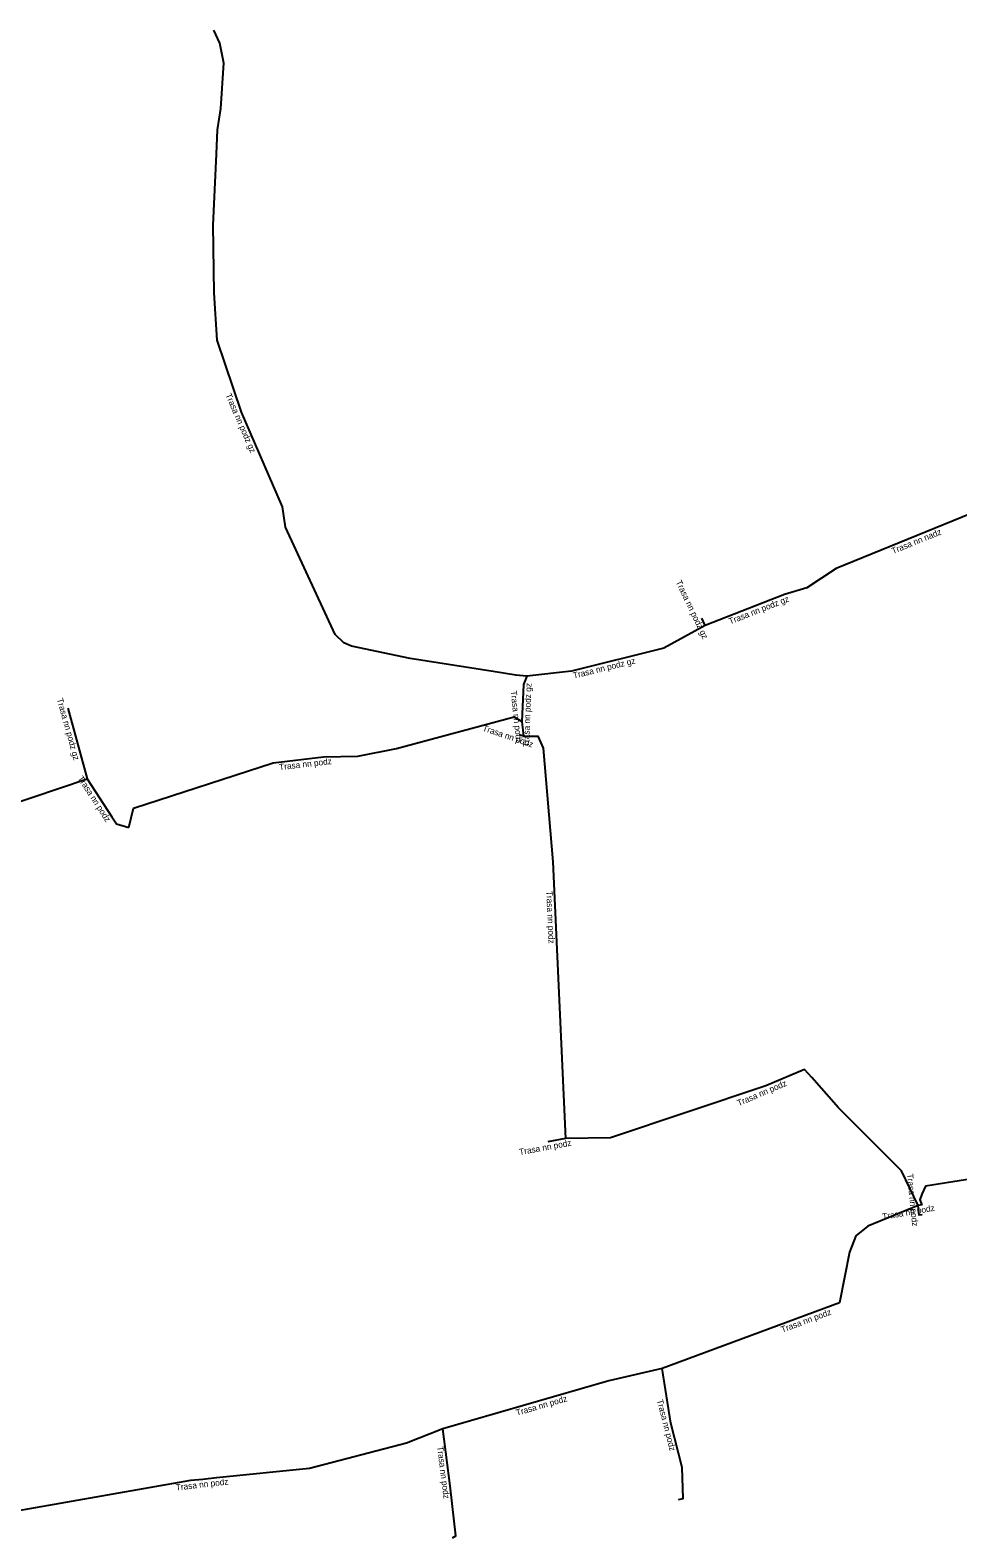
# Model space of a CAD drawing. Extents: x -682605 to -681948, y -1059884 to -1059661.
# Drawn here: x -682078.5 to -682003.5, y -1059783.1 to -1059661.3 of the extents above; entities that cross this region are included whole.
import ezdxf

# ---------------------------------------------------------------- set-up
doc = ezdxf.new("R2010")
doc.units = 0
doc.layers.add('Popiskový text - Ostatní atributy Trasy', color=7, linetype='Continuous')
doc.layers.add('Spojnice NN', color=7, linetype='Continuous')

msp = doc.modelspace()

# ---------------------------------------------------------------- linework, layer by layer
at = {"layer": 'Spojnice NN'}
for points in [[(-682038.37, -1059713.5), (-682039.26, -1059713.42), (-682041.09, -1059713.12), (-682047.78, -1059712.07), (-682052.52, -1059711.08), (-682053.14, -1059710.79), (-682053.84, -1059710.14), (-682057.85, -1059701.45), (-682058.11, -1059699.81), (-682061.41, -1059692.17), (-682063.38, -1059686.35), (-682063.62, -1059682.53), (-682063.69, -1059677.06), (-682063.44, -1059671.32), (-682063.35, -1059669.36), (-682063.08, -1059667.63), (-682062.85, -1059663.98), (-682063.16, -1059662.34), (-682063.64, -1059661.3)], [(-681998.83, -1059698.88), (-682013.37, -1059704.8)], [(-682013.37, -1059704.8), (-682015.73, -1059706.36), (-682017.53, -1059706.9), (-682023.94, -1059709.41)], [(-682023.94, -1059709.41), (-682024.22, -1059708.82)], [(-682023.94, -1059709.41), (-682027.3, -1059711.23), (-682034.75, -1059713.08), (-682038.37, -1059713.5)], [(-682038.37, -1059713.5), (-682038.63, -1059714.17), (-682038.75, -1059717.15)], [(-682075.45, -1059716.08), (-682073.88, -1059721.78)], [(-682070.52, -1059725.73), (-682070.13, -1059724.17), (-682058.84, -1059720.49), (-682054.79, -1059720.02), (-682052, -1059719.96), (-682048.89, -1059719.33), (-682039.37, -1059716.77), (-682038.75, -1059717.15)], [(-682038.75, -1059717.15), (-682038.62, -1059718.35)], [(-682038.62, -1059718.35), (-682038.97, -1059718.23)], [(-682038.62, -1059718.35), (-682037.46, -1059718.35), (-682037.04, -1059719.3), (-682036.25, -1059728.49), (-682035.24, -1059750.85)], [(-682090.02, -1059727.12), (-682082.85, -1059724.8), (-682073.88, -1059721.78)], [(-682073.88, -1059721.78), (-682071.89, -1059724.86), (-682071.52, -1059725.41), (-682070.52, -1059725.73)], [(-682006.74, -1059756.26), (-682008.1, -1059753.47), (-682013.17, -1059748.37), (-682015.33, -1059745.91), (-682015.92, -1059745.26), (-682019.04, -1059746.59), (-682031.61, -1059750.8), (-682035.24, -1059750.85)], [(-681973.04, -1059750.26), (-681976.75, -1059750.5), (-681993.23, -1059752.66), (-682006.15, -1059754.71), (-682006.44, -1059755.34), (-682006.62, -1059755.81), (-682006.45, -1059756.21)], [(-682035.24, -1059750.85), (-682036.66, -1059751.11)], [(-682006.74, -1059756.26), (-682010.82, -1059757.92), (-682011.77, -1059758.71), (-682012.3, -1059760.03), (-682013.09, -1059764.13), (-682027.43, -1059769.44)], [(-682006.45, -1059756.21), (-682006.74, -1059756.26)], [(-682006.42, -1059757), (-682006.66, -1059757.05), (-682006.74, -1059756.26)], [(-682027.43, -1059769.44), (-682031.72, -1059770.43), (-682045.14, -1059774.29)], [(-682026.11, -1059780.01), (-682025.72, -1059779.93), (-682025.8, -1059777.43), (-682026.72, -1059773.84), (-682027.43, -1059769.44)], [(-682045.14, -1059774.29), (-682048.09, -1059775.45), (-682055.93, -1059777.51), (-682063.42, -1059778.26), (-682064.54, -1059778.39), (-682065.53, -1059778.47), (-682082.4, -1059781.44)], [(-682044.37, -1059783.11), (-682044.09, -1059782.95), (-682044.56, -1059778.91), (-682045.14, -1059774.29)]]:
    msp.add_lwpolyline(points, dxfattribs=at)

# ---------------------------------------------------------------- texts
at = {"layer": 'Popiskový text - Ostatní atributy Trasy'}
for s, rotation, p in [('Trasa nn podz gz', 293.3613, (-682062.72, -1059690.77)), ('Trasa nn nadz', 22.1641, (-682008.77, -1059703.63)), ('Trasa nn podz gz', 295.3879, (-682026.34, -1059705.88)), ('Trasa nn podz gz', 21.3841, (-682021.93, -1059709.32)), ('Trasa nn podz gz', 13.9457, (-682034.56, -1059713.7)), ('Trasa nn podz gz', 87.7486, (-682038.18, -1059719.22)), ('Trasa nn podz gz', 285.3996, (-682076.33, -1059715.35)), ('Trasa nn podz', 276.1829, (-682039.67, -1059714.69)), ('Trasa nn podz', 341.0754, (-682041.98, -1059717.88)), ('Trasa nn podz', 6.6195, (-682058.34, -1059721.09)), ('Trasa nn podz', 302.8667, (-682074.67, -1059721.75)), ('Trasa nn podz', 272.5863, (-682036.79, -1059730.85)), ('Trasa nn podz', 23.0877, (-682021.24, -1059748.24)), ('Trasa nn podz', 10.3758, (-682038.93, -1059752.19)), ('Trasa nn podz', 275.7824, (-682007.65, -1059753.71)), ('Trasa nn podz', 9.7824, (-682009.59, -1059757.41)), ('Trasa nn podz', 20.3192, (-682017.72, -1059766.54)), ('Trasa nn podz', 16.0468, (-682039.16, -1059773.25)), ('Trasa nn podz', 284.3737, (-682027.86, -1059771.99)), ('Trasa nn podz', 277.1555, (-682045.61, -1059775.74)), ('Trasa nn podz', 6.6208, (-682066.69, -1059779.29))]:
    msp.add_text(s, height=0.5, rotation=rotation, dxfattribs=at).set_placement(p)

doc.saveas('drawing.dxf')
